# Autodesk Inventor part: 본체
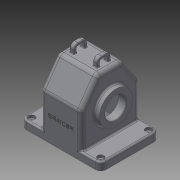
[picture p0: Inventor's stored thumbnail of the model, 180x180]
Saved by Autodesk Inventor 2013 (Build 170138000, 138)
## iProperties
Created: 2016-12
Part Number: 본체
Material: 알루미늄 6061
Document SubType Name: Modeling
Designer: Administrator
Density: 2.71 g/cm^3
Mass: 1110.04 g
Surface Area: 1156.35 cm^2
Volume: 409.61 cm^3
Author: Administrator
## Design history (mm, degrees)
sketch "스케치1"
  geometry: L1 (75, -55)-(-75, -55); L2 (-75, -55)-(-75, 55); L3 (-75, 55)-(75, 55); L4 (75, 55)-(75, -55); L5 (75, -55)-(-75, 55); L6 (-75, -55)-(75, 55); 1 further point
  constraints: 12 end point, 2 midpoint, 2 parallel, 1 horizontal, 1 perpendicular
  dimensions: "d0" = 150 distance of L2.end L3.end; "d1" = 110 distance of L1.end L2.end
extrude "돌출1" new body sketch "스케치1" distance "d2" = 15; taper "d3" = 0 deg
sketch "스케치2"
  geometry: L1 (-38.5, 55)-(38.5, 55); L2 (38.5, 55)-(38.5, -55); L3 (38.5, -55)-(-38.5, -55); L4 (-38.5, -55)-(-38.5, 55); L5 (-38.5, 55)-(38.5, -55); L6 (38.5, 55)-(-38.5, -55); 1 further point
  constraints: 12 end point, 2 midpoint, 2 parallel, 1 horizontal, 1 perpendicular
  dimensions: "d4" = 77 distance of L2.end L3.end; "d5" = 110 distance of L1.end L2.end
extrude "돌출2" join sketch "스케치2" distance "d6" = 110; taper "d7" = 0 deg
chamfer "모따기1" distance "d8" = 45; stored, may be unused: second distance "d9" = 2, angle "d10" = 35 deg
chamfer "모따기2" distance "d11" = 45; stored, may be unused: second distance "d12" = 2, angle "d13" = 35 deg
sketch "스케치3"
  geometry: 1 further point
fillet "모깎기1" dims "d14" = 10
sketch "스케치4"
  geometry: L1 (55, 15)-(55, 76.847) reference; L2 (-55, 15)-(55, 15) reference; L3 (-55, 15)-(-55, 76.847) reference; L4 (-26.477, 120.736)-(-53.192, 82.583) reference; L5 (18.285, 125)-(-18.285, 125) reference; L6 (53.192, 82.583)-(26.477, 120.736) reference; L7 (-50, 76.847)-(-50, 0); L8 (50, 0)-(50, 76.847); L9 (49.096, 79.715)-(22.381, 117.868); L10 (18.285, 120)-(-18.285, 120); L11 (-22.381, 117.868)-(-49.096, 79.715); L12 (-50, 0)-(50, 0); L13 (-55, 0)-(55, 0) reference; A1 r 10 centre (45, 76.847) between (55, 76.847) and (53.192, 82.583) reference; A2 r 10 centre (-45, 76.847) between (-53.192, 82.583) and (-55, 76.847) reference; A3 r 10 centre (-18.285, 115) between (-18.285, 125) and (-26.477, 120.736) reference; A4 r 10 centre (18.285, 115) between (26.477, 120.736) and (18.285, 125) reference; A5 r 5 centre (-45, 76.847) between (-49.096, 79.715) and (-50, 76.847); A6 r 5 centre (45, 76.847) between (50, 76.847) and (49.096, 79.715); A7 r 5 centre (18.285, 115) between (22.381, 117.868) and (18.285, 120); A8 r 5 centre (-18.285, 115) between (-18.285, 120) and (-22.381, 117.868); 1 further point
  constraints: 12 end point, 8 point on circle, 4 centre point, 1 collinear, 1 parallel, 7 other
  dimensions: "d15" = 5 distance between parallel lines of L11 L4; "d16" = 5 distance between parallel lines of L7 L3
extrude "돌출3" cut sketch "스케치4" stored distance "d17" = 67; taper "d18" = 0 deg
fillet "모깎기2" dims "d19" = 8
fillet "모깎기3" dims "d20" = 3
fillet "모깎기4" dims "d21" = 10
sketch "스케치5"
  geometry: A1 r 10 centre (-65, 45) between (-65, 55) and (-75, 45) reference; A2 r 10 centre (-65, -45) between (-75, -45) and (-65, -55) reference; 1 further point
sketch "스케치6"
  geometry: A1 r 10 centre (65, 45) between (75, 45) and (65, 55) reference; A2 r 10 centre (65, -45) between (65, -55) and (75, -45) reference; 1 further point
hole "구멍1" sketch "스케치5" diameter "d22" = 5; stored, may be unused: countersink angle "d26" = 90 deg, drill point angle "d28" = 118 deg; dims "d23" = 6, "d24" = 12, "d25" = 5, "d27" = 8
hole "구멍2" sketch "스케치6" diameter "d29" = 5; stored, may be unused: countersink angle "d33" = 90 deg, drill point angle "d35" = 118 deg; dims "d30" = 6, "d31" = 12, "d32" = 5, "d34" = 8
node "작업 평면1"
sketch "스케치7"
  geometry: L1 (-12.5, 140)-(12.5, 140); L2 (12.5, 140)-(12.5, 125); L3 (12.5, 125)-(-12.5, 125); L4 (-12.5, 125)-(-12.5, 140); L5 (47, 0)-(-47, 0) reference; L6 (-18.285, 125)-(18.285, 125) reference; L7 (-7.5, 135)-(7.5, 135); L8 (7.5, 135)-(7.5, 125); L9 (7.5, 125)-(-7.5, 125); L10 (-7.5, 125)-(-7.5, 135); 5 further points
  constraints: 16 end point, 4 midpoint, 4 parallel, 2 collinear, 2 horizontal, 2 perpendicular, 1 coincident, 1 vertical alignment
  dimensions: "d37" = 140 distance between parallel lines of L1 L5; "d38" = 25 distance of L1.start L1.end; "d39" = 15 distance of L7.start L7.end; "d40" = 5 distance between parallel lines of L1 L7
extrude "돌출4" join sketch "스케치7" distance "d41" = 8; taper "d42" = 0 deg
fillet "모깎기5" dims "d43" = 8
fillet "모깎기6" dims "d44" = 3
fillet "모깎기7" dims "d45" = 1
fillet "모깎기8" dims "d46" = 1
fillet "모깎기9" dims "d47" = 3
fillet "모깎기10" dims "d48" = 3
sketch "스케치8"
  geometry: L1 (117, 63.285)-(117, -26.715) reference; C1 r 31 at (52, 18.285); 2 further points
  constraints: 1 centre point, 1 horizontal alignment, 1 midpoint
  dimensions: "d49" = 62 diameter of C1; "d50" = 65 distance from line of C1.centre L1
extrude "돌출5" join sketch "스케치8" distance "d51" = 10; taper "d52" = 0 deg
sketch "스케치9"
  geometry: L1 (33.5, 106)-(19.5, 92); L2 (19.5, 92)-(19.5, 65); L3 (33.5, 65)-(33.5, 106); L4 (33.5, 65)-(19.5, 65); L5 (-30.5, 0)-(30.5, 0) reference; L6 (33.5, 116.147)-(33.5, 77.994) reference; 1 further point
  constraints: 8 end point, 1 collinear, 1 horizontal, 1 parallel, 1 vertical
  dimensions: "d53" = 65 distance between parallel lines of L4 L5; "d54" = 54 diameter of L1.end L4; "d55" = 45 deg angle of L1 L2; "d56" = 14 distance of L3.start L2.end
revolve "회전1" sketch "스케치9" stored, may be unused: angle "d57" = 90 deg
sketch "스케치10"
  geometry: C1 r 31 at (-52, 18.285) reference; C2 r 37.5 at (-52, 18.285); 1 further point
  constraints: 1 centre point, 1 coincident
  dimensions: "d58" = 75 diameter of C2
extrude "돌출6" join sketch "스케치10" distance "d59" = 5; taper "d60" = 0 deg
hole "구멍3" diameter "d63" = 40; stored, may be unused: countersink angle "d67" = 90 deg, drill point angle "d69" = 118 deg; dims "d61" = 10, "d62" = 10, "d64" = 6, "d65" = 12, "d66" = 5, "d68" = 8
sketch "스케치11"
  geometry: C1 r 20 at (0, 0) reference; 2 further points
  constraints: 1 horizontal alignment
  dimensions: "d70" = 29 distance of C1.centre point (29, 0)
hole "구멍4" sketch "스케치11" at (29, 0) diameter "d71" = 2.459; stored, may be unused: countersink angle "d75" = 90 deg, drill point angle "d77" = 118 deg; dims "d72" = 6, "d73" = 12, "d74" = 5, "d76" = 8
sketch "스케치12"
  geometry: C1 r 20 at (0, 0) reference; 2 further points
  constraints: 1 horizontal alignment
  dimensions: "d81" = 26 distance of C1.centre point (-26, 0)
hole "구멍5" sketch "스케치12" at (-26, 0) diameter "d82" = 2.459; stored, may be unused: countersink angle "d86" = 90 deg, drill point angle "d88" = 118 deg; dims "d83" = 6, "d84" = 12, "d85" = 5, "d87" = 8
fillet "모깎기11" dims "d92" = 3
chamfer "모따기3" distance "d93" = 1; stored, may be unused: second distance "d94" = 2, angle "d95" = 35 deg
sketch "스케치13"
  geometry: L1 (5.369, -28.302)-(55.631, -28.302); L2 (55.631, -28.302)-(55.631, -35.392); L3 (55.631, -35.392)-(5.369, -35.392); L4 (5.369, -35.392)-(5.369, -28.302); L5 (5.369, -31.847)-(55.631, -31.847); L6 (30.5, -28.302)-(30.5, -31.847); L7 (30.5, -76.847)-(30.5, -31.847); L8 (-8, 0)-(-8, -58.847) reference
  constraints: 6 end point, 4 midpoint, 1 collinear, 1 vertical, 2 other
  dimensions: "d96" = 45 distance of L7.start L7.end; "d97" = 38.5 distance between parallel lines of L6 L8
feature "엠보싱1" sketch "스케치13" dims "d98" = 0.5, "d99" = 0
fillet "모깎기12" dims "d100" = 3
node "솔리드1"
mirror "대칭1"
pattern_circular "원형 패턴1" dims angle "d79" = 360 deg
pattern_circular "원형 패턴2" dims angle "d90" = 360 deg
node "투영된 루프1"
other parameters: "d36" = 18
